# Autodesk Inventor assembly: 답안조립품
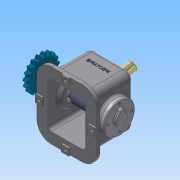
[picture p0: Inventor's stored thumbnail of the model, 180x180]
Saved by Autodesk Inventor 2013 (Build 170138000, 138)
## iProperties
Created: 2014-11
Part Number: 답안조립품
Document SubType Name: Assembly
Designer: Administrator
Author: Administrator
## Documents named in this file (13)
- C:\Users\Administrator\Desktop\441123V1027\답안조립품.iam
- C:\Users\Administrator\Desktop\441123V1027\5-체인 스프로킷.ipt
- C:\Users\Administrator\Desktop\441123V1027\M4x0.5.ipt
- C:\Users\Administrator\Desktop\441123V1027\뒤커버.ipt
- C:\Users\Administrator\Desktop\441123V1027\멈춤나사 M5x0.5.ipt
- C:\Users\Administrator\Desktop\441123V1027\베어링 6205.ipt
- C:\Users\Administrator\Desktop\441123V1027\본체.ipt
- C:\Users\Administrator\Desktop\441123V1027\부시.ipt
- C:\Users\Administrator\Desktop\441123V1027\슬라이드.ipt
- C:\Users\Administrator\Desktop\441123V1027\앞커버.ipt
- C:\Users\Administrator\Desktop\441123V1027\오일실.ipt
- C:\Users\Administrator\Desktop\441123V1027\키 8x8.ipt
- C:\Users\Administrator\Desktop\441123V1027\편심축.ipt
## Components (9 placed, 2 different names)
1. 5-체인 스프로킷:1 — 플러쉬:2
2. M4x0.5:2
3. M4x0.5:3
4. M4x0.5:4
5. M4x0.5:5
6. M4x0.5:1
7. M4x0.5:6
8. M4x0.5:7
9. M4x0.5:8
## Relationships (1: Flush 1)
- 플러쉬:2 [Flush]: 5-체인 스프로킷:1
